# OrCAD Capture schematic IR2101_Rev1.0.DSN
size A4; title: IR1201 Gate Driver; rev: V1.0
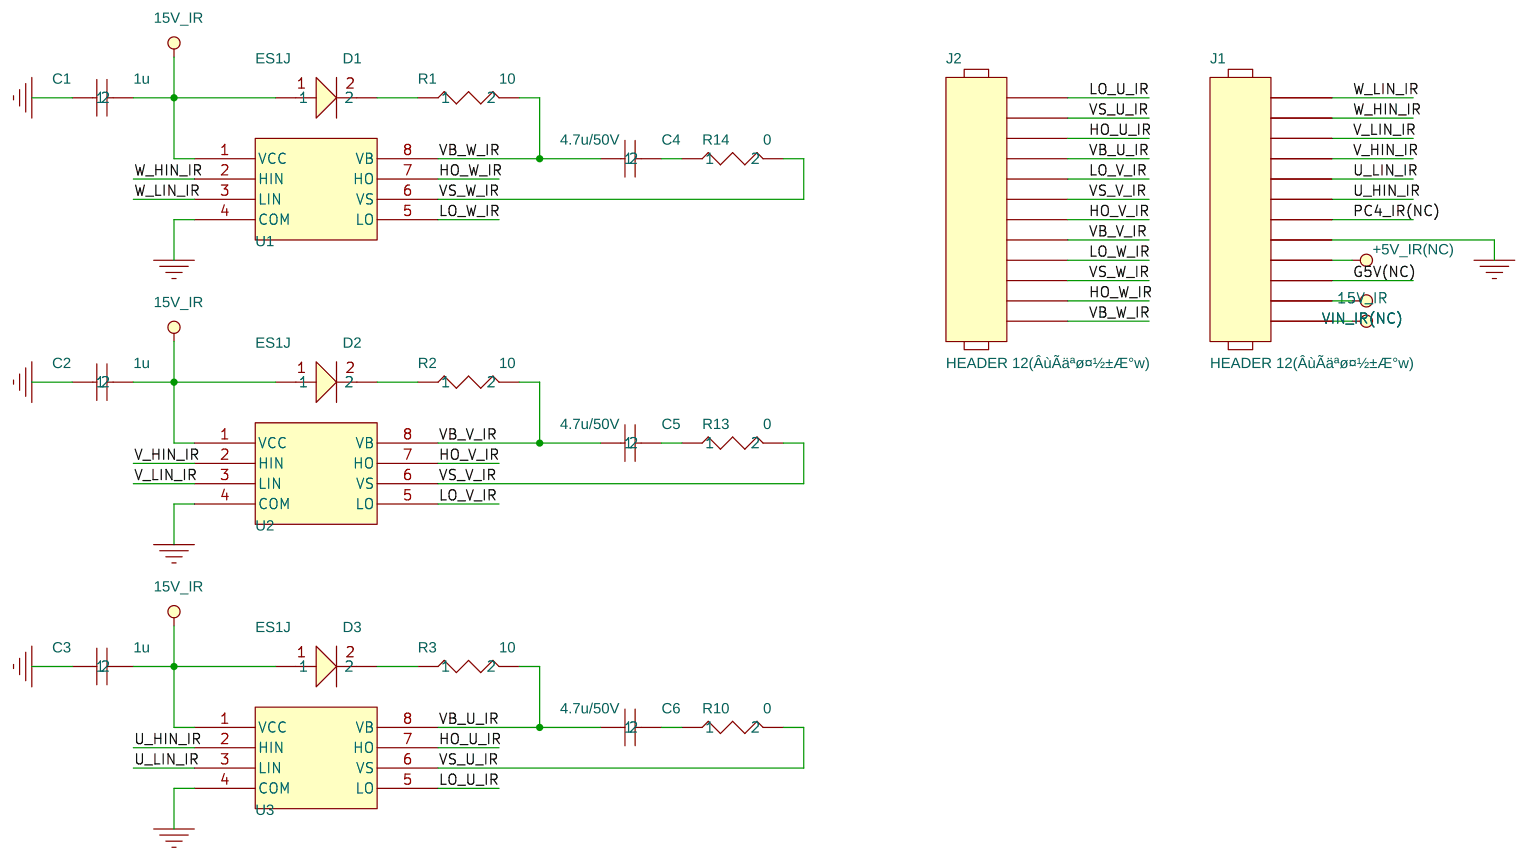
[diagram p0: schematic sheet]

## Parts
C1  1u  [C0603]
C2  1u  [C0603]
C3  1u  [C0603]
C4  4.7u/50V  [C1206]
C5  4.7u/50V  [C1206]
C6  4.7u/50V  [C1206]
D1  ES1J  [RB060L]
D2  ES1J  [RB060L]
D3  ES1J  [RB060L]
J1  HEADER 12(ÂùÃäªø¤½±Æ°w)  [HEADER12x1]
J2  HEADER 12(ÂùÃäªø¤½±Æ°w)  [HEADER12x1]
R1  10  [R0603]
R2  10  [R0603]
R3  10  [R0603]
R10  0  [R0603]
R13  0  [R0603]
R14  0  [R0603]
U1  NM1530VE3AE  [SO-8]
U2  NM1530VE3AE  [SO-8]
U3  NM1530VE3AE  [SO-8]

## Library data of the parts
C1 = C_0.1u_1
C2 = C_0.1u_2
C3 = C_0.1u
C4 = C_0.1u_3
C5 = C_0.1u_5
C6 = C_0.1u_4
D1 = D_SS24A_5_1
D2 = D_SS24A_5
D3 = D_SS24A_5_2
J1 J2 = HEADER_12
R1 = R_33_2
R2 = R_33_1
R3 = R_33
R10 = R_33_4
R13 = R_33_3
R14 = R_33_5
U1-U3 = NM1530VE3AE_0

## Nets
15V_IR: C1.2 C2.2 C3.2 D1.1 D2.1 D3.1 J1.11 U1.1(VCC) U2.1(VCC) U3.1(VCC)
+5V_IR(NC): J1.9
GND_IR: C1.1 C2.1 C3.1 J1.8 U1.4(COM) U2.4(COM) U3.4(COM)
VIN_IR(NC): J1.12
G5V(NC): J1.10
HO_U_IR: J2.3 U3.7(HO)
HO_V_IR: J2.7 U2.7(HO)
HO_W_IR: J2.11 U1.7(HO)
LO_U_IR: J2.1 U3.5(LO)
LO_V_IR: J2.5 U2.5(LO)
LO_W_IR: J2.9 U1.5(LO)
PC4_IR(NC): J1.7
U_HIN_IR: J1.6 U3.2(HIN)
U_LIN_IR: J1.5 U3.3(LIN)
V_HIN_IR: J1.4 U2.2(HIN)
V_LIN_IR: J1.3 U2.3(LIN)
VB_U_IR: C6.1 J2.4 R3.2 U3.8(VB)
VB_V_IR: C5.1 J2.8 R2.2 U2.8(VB)
VB_W_IR: C4.1 J2.12 R1.2 U1.8(VB)
VS_U_IR: J2.2 R10.2 U3.6(VS)
VS_V_IR: J2.6 R13.2 U2.6(VS)
VS_W_IR: J2.10 R14.2 U1.6(VS)
W_HIN_IR: J1.2 U1.2(HIN)
W_LIN_IR: J1.1 U1.3(LIN)
N26613: C6.2 R10.1
N26617: C5.2 R13.1
N26621: C4.2 R14.1
N21541785: D1.2 R1.1
N21541937: D2.2 R2.1
N21542078: D3.2 R3.1
